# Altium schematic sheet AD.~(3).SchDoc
size A4
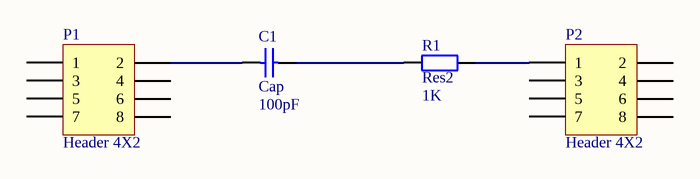
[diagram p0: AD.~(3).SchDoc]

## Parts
C1  Cap  value 100pF  [RAD-0.3]
P1  Header 4X2  [HDR2X4]
P2  Header 4X2  [HDR2X4]
R1  Res2  value 1K  [AXIAL-0.4]

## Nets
NetC1_1: C1.1 P1.2
NetC1_2: C1.2 R1.1
NetP2_1: P2.1 R1.2

Not connected (* = marked no-connect by the designer): P1 1 3 4 5 6 7 8; P2 2 3 4 5 6 7 8

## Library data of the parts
C1 = Cap: Capacitor
P1 P2 = Header 4X2: Header, 4-Pin, Dual row
R1 = Res2: Resistor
